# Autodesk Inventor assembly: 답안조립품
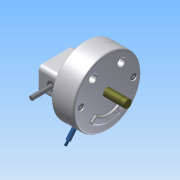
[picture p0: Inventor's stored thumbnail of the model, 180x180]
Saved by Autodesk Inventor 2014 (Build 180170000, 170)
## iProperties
Created: 2015-04
Part Number: 답안조립품
Document SubType Name: Assembly
Designer: Administrator
Mass: 3965.01 g
Surface Area: 3333.71 cm^2
Volume: 1140.86 cm^3
Density: 3.47546 g/cm^3
Author: Administrator
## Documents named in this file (15)
- C:\Documents and Settings\Administrator\바탕 화면\350406V1014\답안조립품.iam
- C:\Documents and Settings\Administrator\바탕 화면\350406V1014\본체.ipt
- C:\Documents and Settings\Administrator\바탕 화면\350406V1014\커버.ipt
- C:\Documents and Settings\Administrator\바탕 화면\350406V1014\M 10 x 35.ipt
- C:\Documents and Settings\Administrator\바탕 화면\350406V1014\베어링62_22.ipt
- C:\Documents and Settings\Administrator\바탕 화면\350406V1014\커버2.ipt
- C:\Documents and Settings\Administrator\바탕 화면\350406V1014\스프링.ipt
- C:\Documents and Settings\Administrator\바탕 화면\350406V1014\축.ipt
- C:\Documents and Settings\Administrator\바탕 화면\350406V1014\멈춤링.ipt
- C:\Documents and Settings\Administrator\바탕 화면\350406V1014\슬라이더2.ipt
- C:\Documents and Settings\Administrator\바탕 화면\350406V1014\슬라이더.ipt
- C:\Documents and Settings\Administrator\바탕 화면\350406V1014\평행핀.ipt
- C:\Documents and Settings\Administrator\바탕 화면\350406V1014\부시.ipt
- C:\Documents and Settings\Administrator\바탕 화면\350406V1014\M 5 x 12.ipt
- C:\Documents and Settings\Administrator\바탕 화면\350406V1014\슬라이더3.ipt
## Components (5 placed, 3 different names)
1. M 10 x 35:1
2. M 10 x 35:2
3. KS B 1320 B B 5 x  20:1
4. M 5 x 12:1
5. M 5 x 12:2
